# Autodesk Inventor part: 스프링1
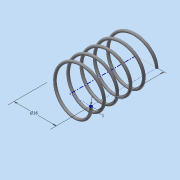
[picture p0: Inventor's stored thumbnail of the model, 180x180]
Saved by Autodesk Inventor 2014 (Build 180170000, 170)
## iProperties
Created: 2015-06
Part Number: 스프링1
Material: 강철, 연강
Document SubType Name: Modeling
Designer: MYHOME
Density: 7.86 g/cm^3
Appearance: 강철
Mass: 1.5292 g
Surface Area: 7.8715 cm^2
Volume: 0.194555 cm^3
Author: MYHOME
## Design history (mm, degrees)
sketch "스케치1"
  geometry: L1 (0, 0)-(8, 0); L2 (8, 0)-(8, 14.5); L3 (8, 14.5)-(0, 14.5); L4 (0, 14.5)-(0, 0); C1 r 0.5 at (8, 0)
  constraints: 8 end point, 2 parallel, 1 centre point, 1 coincident, 1 horizontal, 1 perpendicular
  dimensions: "d0" = 16 diameter of L2 L4; "d1" = 14.5 distance of L1.end L2.end (derived); "d2" = 1 diameter of C1
feature "코일1" sketch "스케치1" pitch "d3" = 10; turns "d5" = 5; dims "d4" = 14.5 (= d1), "d6" = 0, angle "d7" = 90 deg, angle "d8" = 90 deg, "d9" = 0, "d10" = 0
node "작업 평면1"
sketch "스케치2"
  geometry: L1 (-8.5, 0)-(-7.5, 0) reference; 1 further point
  constraints: 1 horizontal alignment
extrude "돌출1" cut sketch "스케치2" stored distance "d12" = 10; taper "d13" = 0 deg
node "작업 평면2"
sketch "스케치3"
  geometry: L1 (8.5, 0)-(7.5, 0) reference; 1 further point
  constraints: 1 horizontal alignment
extrude "돌출2" cut sketch "스케치3" stored distance "d15" = 10; taper "d16" = 0 deg
node "솔리드1"
node "절단 모서리 투영1"
node "절단 모서리 투영2"
other parameters: "d11" = 0, "d14" = -14.5 (= -d1)
